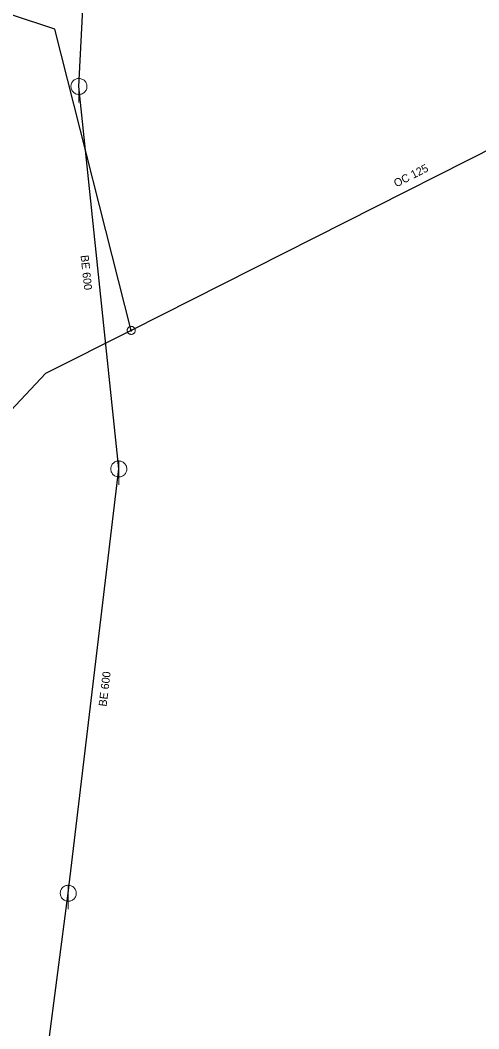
# Model space of a CAD drawing. Extents: x -659250 to -657316, y -997555 to -993684.
# Drawn here: x -658547.5 to -658490.2, y -994219.6 to -994093.6 of the extents above; entities that cross this region are included whole.
import ezdxf

# ---------------------------------------------------------------- set-up
doc = ezdxf.new("R2010")
doc.units = 0
doc.header["$LTSCALE"] = 0.4
doc.layers.add('1', color=7, linetype='Continuous')
for name, color, linetype, lineweight in [('14', 7, 'Continuous', 25), ('17', 7, 'Continuous', 25), ('22', 7, 'Continuous', 13), ('47', 7, 'Continuous', 13)]:
    doc.layers.add(name, color=color, linetype=linetype, lineweight=lineweight)

msp = doc.modelspace()

# ---------------------------------------------------------------- linework, layer by layer
at = {"layer": '14'}
for p, q in [((-658535.18, -994149.69), (-658540.16, -994101.91)), ((-658541.489, -994202.69), (-658535.18, -994149.69)), ((-658547.12, -994245.69), (-658541.489, -994202.69))]:
    msp.add_line(p, q, dxfattribs=at)
msp.add_lwpolyline([(-658540.16, -994101.91), (-658538.859, -994075.98), (-658530.149, -994054.649)], dxfattribs=at)
at = {"layer": '17'}
for points in [[(-658533.629, -994132.381), (-658543.176, -994094.762), (-658576.06, -994083.83), (-658559.027, -994037.098), (-658707.828, -993955.756)], [(-658461.26, -994095.324), (-658461.175, -994095.73), (-658533.629, -994132.381)], [(-658533.629, -994132.381), (-658544.322, -994137.752), (-658562.909, -994157.543)]]:
    msp.add_lwpolyline(points, dxfattribs=at)
at = {"layer": '22'}
for p, q in [((-658540.16, -994103.91), (-658540.159, -994100.91)), ((-658535.18, -994151.69), (-658535.179, -994148.69)), ((-658541.49, -994204.69), (-658541.489, -994201.69))]:
    msp.add_line(p, q, dxfattribs=at)
for points in [[(-658539.16, -994101.91), (-658539.165, -994101.801), (-658539.183, -994101.693), (-658539.213, -994101.587), (-658539.253, -994101.486), (-658539.305, -994101.389), (-658539.367, -994101.299), (-658539.439, -994101.216), (-658539.519, -994101.142), (-658539.607, -994101.076), (-658539.701, -994101.021), (-658539.801, -994100.976), (-658539.906, -994100.943), (-658540.013, -994100.921), (-658540.122, -994100.911), (-658540.232, -994100.913), (-658540.34, -994100.927), (-658540.447, -994100.952), (-658540.55, -994100.989), (-658540.648, -994101.038), (-658540.74, -994101.096), (-658540.826, -994101.165), (-658540.903, -994101.242), (-658540.972, -994101.328), (-658541.031, -994101.42), (-658541.079, -994101.518), (-658541.116, -994101.621), (-658541.142, -994101.728), (-658541.156, -994101.836), (-658541.159, -994101.946), (-658541.149, -994102.055), (-658541.128, -994102.162), (-658541.094, -994102.266), (-658541.05, -994102.366), (-658540.995, -994102.461), (-658540.929, -994102.549), (-658540.855, -994102.629), (-658540.772, -994102.701), (-658540.682, -994102.763), (-658540.586, -994102.815), (-658540.484, -994102.856), (-658540.379, -994102.886), (-658540.271, -994102.904), (-658540.161, -994102.91), (-658540.052, -994102.904), (-658539.944, -994102.886), (-658539.839, -994102.857), (-658539.737, -994102.816), (-658539.64, -994102.764), (-658539.55, -994102.702), (-658539.467, -994102.631), (-658539.392, -994102.551), (-658539.327, -994102.463), (-658539.271, -994102.369), (-658539.227, -994102.269), (-658539.193, -994102.165), (-658539.171, -994102.057), (-658539.161, -994101.948)], [(-658534.18, -994149.69), (-658534.185, -994149.581), (-658534.203, -994149.473), (-658534.233, -994149.367), (-658534.273, -994149.266), (-658534.325, -994149.169), (-658534.387, -994149.079), (-658534.459, -994148.996), (-658534.539, -994148.922), (-658534.627, -994148.856), (-658534.721, -994148.801), (-658534.821, -994148.756), (-658534.926, -994148.723), (-658535.033, -994148.701), (-658535.142, -994148.691), (-658535.252, -994148.693), (-658535.36, -994148.707), (-658535.467, -994148.732), (-658535.57, -994148.769), (-658535.668, -994148.818), (-658535.76, -994148.876), (-658535.846, -994148.945), (-658535.923, -994149.022), (-658535.992, -994149.108), (-658536.051, -994149.2), (-658536.099, -994149.298), (-658536.136, -994149.401), (-658536.162, -994149.508), (-658536.176, -994149.616), (-658536.179, -994149.726), (-658536.169, -994149.835), (-658536.148, -994149.942), (-658536.114, -994150.046), (-658536.07, -994150.146), (-658536.015, -994150.241), (-658535.949, -994150.329), (-658535.875, -994150.409), (-658535.792, -994150.481), (-658535.702, -994150.543), (-658535.606, -994150.595), (-658535.504, -994150.636), (-658535.399, -994150.666), (-658535.291, -994150.684), (-658535.181, -994150.69), (-658535.072, -994150.684), (-658534.964, -994150.666), (-658534.859, -994150.637), (-658534.757, -994150.596), (-658534.66, -994150.544), (-658534.57, -994150.482), (-658534.487, -994150.411), (-658534.412, -994150.331), (-658534.347, -994150.243), (-658534.291, -994150.149), (-658534.247, -994150.049), (-658534.213, -994149.945), (-658534.191, -994149.837), (-658534.181, -994149.728)], [(-658540.49, -994202.69), (-658540.495, -994202.581), (-658540.513, -994202.473), (-658540.543, -994202.367), (-658540.583, -994202.266), (-658540.635, -994202.169), (-658540.697, -994202.079), (-658540.769, -994201.996), (-658540.849, -994201.922), (-658540.937, -994201.856), (-658541.031, -994201.801), (-658541.131, -994201.756), (-658541.236, -994201.723), (-658541.343, -994201.701), (-658541.452, -994201.691), (-658541.562, -994201.693), (-658541.67, -994201.707), (-658541.777, -994201.732), (-658541.88, -994201.769), (-658541.978, -994201.818), (-658542.07, -994201.876), (-658542.156, -994201.945), (-658542.233, -994202.022), (-658542.302, -994202.108), (-658542.361, -994202.2), (-658542.409, -994202.298), (-658542.446, -994202.401), (-658542.472, -994202.508), (-658542.486, -994202.616), (-658542.489, -994202.726), (-658542.479, -994202.835), (-658542.458, -994202.942), (-658542.424, -994203.046), (-658542.38, -994203.146), (-658542.325, -994203.241), (-658542.259, -994203.329), (-658542.185, -994203.409), (-658542.102, -994203.481), (-658542.012, -994203.543), (-658541.916, -994203.595), (-658541.814, -994203.636), (-658541.709, -994203.666), (-658541.601, -994203.684), (-658541.491, -994203.69), (-658541.382, -994203.684), (-658541.274, -994203.666), (-658541.169, -994203.637), (-658541.067, -994203.596), (-658540.97, -994203.544), (-658540.88, -994203.482), (-658540.797, -994203.411), (-658540.722, -994203.331), (-658540.657, -994203.243), (-658540.601, -994203.149), (-658540.557, -994203.049), (-658540.523, -994202.945), (-658540.501, -994202.837), (-658540.491, -994202.728)]]:
    msp.add_lwpolyline(points, close=True, dxfattribs=at)
at = {"layer": '47'}
for points in [[(-658533.129, -994132.381), (-658533.132, -994132.329), (-658533.14, -994132.277), (-658533.154, -994132.227), (-658533.171, -994132.178), (-658533.196, -994132.131), (-658533.225, -994132.087), (-658533.257, -994132.047), (-658533.294, -994132.01), (-658533.335, -994131.977), (-658533.379, -994131.948), (-658533.426, -994131.924), (-658533.475, -994131.906), (-658533.524, -994131.892), (-658533.576, -994131.884), (-658533.629, -994131.881), (-658533.681, -994131.884), (-658533.733, -994131.892), (-658533.784, -994131.906), (-658533.831, -994131.924), (-658533.879, -994131.948), (-658533.923, -994131.977), (-658533.963, -994132.01), (-658534, -994132.047), (-658534.034, -994132.087), (-658534.061, -994132.131), (-658534.086, -994132.178), (-658534.105, -994132.227), (-658534.117, -994132.277), (-658534.125, -994132.329), (-658534.129, -994132.381), (-658534.125, -994132.433), (-658534.117, -994132.485), (-658534.105, -994132.536), (-658534.086, -994132.584), (-658534.061, -994132.631), (-658534.034, -994132.675), (-658534, -994132.716), (-658533.963, -994132.753), (-658533.923, -994132.786), (-658533.879, -994132.814), (-658533.831, -994132.838), (-658533.784, -994132.857), (-658533.733, -994132.87), (-658533.681, -994132.878), (-658533.629, -994132.881), (-658533.576, -994132.878), (-658533.524, -994132.87), (-658533.475, -994132.857), (-658533.426, -994132.838), (-658533.379, -994132.814), (-658533.335, -994132.786), (-658533.294, -994132.753), (-658533.257, -994132.716), (-658533.225, -994132.675), (-658533.196, -994132.631), (-658533.171, -994132.584), (-658533.154, -994132.536), (-658533.14, -994132.485), (-658533.132, -994132.433)], [(-658533.546, -994132.381), (-658533.546, -994132.372), (-658533.549, -994132.364), (-658533.551, -994132.356), (-658533.554, -994132.348), (-658533.558, -994132.34), (-658533.563, -994132.333), (-658533.568, -994132.326), (-658533.573, -994132.32), (-658533.581, -994132.315), (-658533.588, -994132.31), (-658533.595, -994132.306), (-658533.603, -994132.303), (-658533.612, -994132.301), (-658533.62, -994132.299), (-658533.629, -994132.299), (-658533.637, -994132.299), (-658533.646, -994132.301), (-658533.654, -994132.303), (-658533.662, -994132.306), (-658533.669, -994132.31), (-658533.676, -994132.315), (-658533.684, -994132.32), (-658533.69, -994132.326), (-658533.696, -994132.333), (-658533.7, -994132.34), (-658533.703, -994132.348), (-658533.706, -994132.356), (-658533.708, -994132.364), (-658533.711, -994132.372), (-658533.711, -994132.381), (-658533.711, -994132.39), (-658533.708, -994132.398), (-658533.706, -994132.406), (-658533.703, -994132.414), (-658533.7, -994132.422), (-658533.696, -994132.429), (-658533.69, -994132.436), (-658533.684, -994132.442), (-658533.676, -994132.448), (-658533.669, -994132.452), (-658533.662, -994132.456), (-658533.654, -994132.459), (-658533.646, -994132.461), (-658533.637, -994132.463), (-658533.629, -994132.463), (-658533.62, -994132.463), (-658533.612, -994132.461), (-658533.603, -994132.459), (-658533.595, -994132.456), (-658533.588, -994132.452), (-658533.581, -994132.448), (-658533.573, -994132.442), (-658533.568, -994132.436), (-658533.563, -994132.429), (-658533.558, -994132.422), (-658533.554, -994132.414), (-658533.551, -994132.406), (-658533.549, -994132.398), (-658533.546, -994132.39)]]:
    msp.add_lwpolyline(points, close=True, dxfattribs=at)

# ---------------------------------------------------------------- texts
at = {"layer": '1'}
for s, rotation, p in [('OC 125', 27, (-658500.523, -994114.53)), ('BE 600', 276, (-658539.955, -994123.02)), ('BE 600', 83, (-658536.718, -994179.403))]:
    msp.add_text(s, height=1, rotation=rotation, dxfattribs=at).set_placement(p)

doc.saveas('drawing.dxf')
